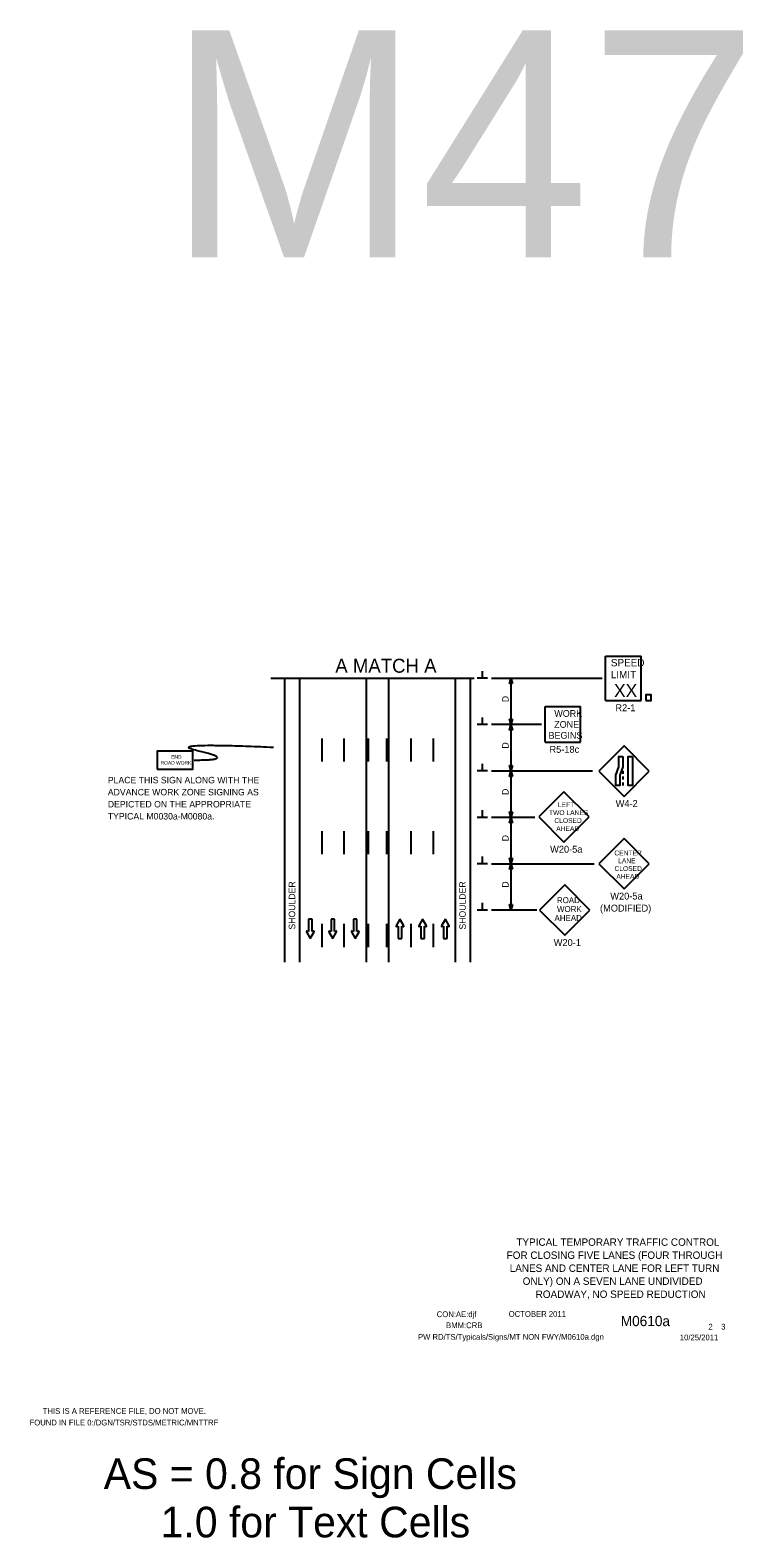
# Model space of a CAD drawing. Extents: x 16646 to 19498, y 2812 to 4437.
# Drawn here: x 17675 to 18443, y 2812 to 4437 of the extents above; entities that cross this region are included whole.
import ezdxf

# ---------------------------------------------------------------- set-up
doc = ezdxf.new("R2010")
doc.units = 0
for name, color, linetype in [('ALI_LEGAL_EX', 7, 'Continuous'), ('BORDER', 7, 'Continuous'), ('BORDER_SIGNAL_WO', 7, 'Continuous'), ('MT_SCRATCH_LEVEL_E', 7, 'Continuous'), ('PAVT_EDGE_EX', 7, 'Continuous'), ('SCRATCH_LEVEL_A', 7, 'Continuous'), ('TRAFFIC_SIGNS_PR', 7, 'Continuous'), ('TYPICAL_TEXT_DIMEN_PR', 7, 'Continuous')]:
    doc.layers.add(name, color=color, linetype=linetype)

msp = doc.modelspace()

# ---------------------------------------------------------------- linework, layer by layer
at = {"layer": 'ALI_LEGAL_EX'}
for points in [[(17989.2, 3673.8), (17989.2, 3648.8)], [(18013.2, 3673.8), (18013.2, 3648.8)], [(18039.2, 3673.8), (18039.2, 3648.8)], [(18059.2, 3673.8), (18059.2, 3648.8)], [(18085.2, 3673.8), (18085.2, 3648.8)], [(18109.2, 3673.8), (18109.2, 3648.8)], [(17989.2, 3573.8), (17989.2, 3548.8)], [(18013.2, 3573.8), (18013.2, 3548.8)], [(18039.2, 3573.8), (18039.2, 3548.8)], [(18059.2, 3573.8), (18059.2, 3548.8)], [(18085.2, 3573.8), (18085.2, 3548.8)], [(18109.2, 3573.8), (18109.2, 3548.8)], [(17989.2, 3473.8), (17989.2, 3448.8)], [(18013.2, 3473.8), (18013.2, 3448.8)], [(18039.2, 3473.8), (18039.2, 3448.8)], [(18059.2, 3473.8), (18059.2, 3448.8)], [(18085.2, 3473.8), (18085.2, 3448.8)], [(18109.2, 3473.8), (18109.2, 3448.8)]]:
    msp.add_lwpolyline(points, dxfattribs=at)
at = {"layer": 'MT_SCRATCH_LEVEL_E'}
for p, q in [((17972.7, 3465.1), (17976.8, 3457.9)), ((17972.7, 3465.1), (17976.8, 3457.9)), ((17974.9, 3465.5), (17973.1, 3465.8)), ((17974.9, 3465.5), (17973.1, 3465.8)), ((17978.7, 3478.8), (17974.9, 3478.8)), ((17974.9, 3478.8), (17974.9, 3465.5)), ((17978.7, 3478.8), (17974.9, 3478.8)), ((17974.9, 3478.8), (17974.9, 3465.5)), ((17976.8, 3457.9), (17980.9, 3465.1)), ((17976.8, 3457.9), (17980.9, 3465.1)), ((17978.7, 3465.5), (17978.7, 3478.8)), ((17978.7, 3465.5), (17978.7, 3478.8)), ((17980.4, 3465.8), (17978.7, 3465.5)), ((17980.4, 3465.8), (17978.7, 3465.5)), ((17996.9, 3465.1), (18001.1, 3457.9)), ((17996.9, 3465.1), (18001.1, 3457.9)), ((17999.2, 3465.5), (17997.4, 3465.8)), ((17999.2, 3465.5), (17997.4, 3465.8)), ((18002.9, 3478.8), (17999.2, 3478.8)), ((17999.2, 3478.8), (17999.2, 3465.5)), ((18002.9, 3478.8), (17999.2, 3478.8)), ((17999.2, 3478.8), (17999.2, 3465.5)), ((18001.1, 3457.9), (18005.2, 3465.1)), ((18001.1, 3457.9), (18005.2, 3465.1)), ((18002.9, 3465.5), (18002.9, 3478.8)), ((18002.9, 3465.5), (18002.9, 3478.8)), ((18004.7, 3465.8), (18002.9, 3465.5)), ((18004.7, 3465.8), (18002.9, 3465.5)), ((18021.2, 3465.1), (18025.3, 3457.9)), ((18021.2, 3465.1), (18025.3, 3457.9)), ((18023.4, 3465.5), (18021.6, 3465.8)), ((18023.4, 3465.5), (18021.6, 3465.8)), ((18027.2, 3478.8), (18023.4, 3478.8)), ((18023.4, 3478.8), (18023.4, 3465.5)), ((18027.2, 3478.8), (18023.4, 3478.8)), ((18023.4, 3478.8), (18023.4, 3465.5)), ((18025.3, 3457.9), (18029.4, 3465.1)), ((18025.3, 3457.9), (18029.4, 3465.1)), ((18027.2, 3465.5), (18027.2, 3478.8)), ((18027.2, 3465.5), (18027.2, 3478.8)), ((18028.9, 3465.8), (18027.2, 3465.5)), ((18028.9, 3465.8), (18027.2, 3465.5)), ((18073.5, 3478.8), (18069.4, 3471.5)), ((18073.5, 3478.8), (18069.4, 3471.5)), ((18069.9, 3470.8), (18071.6, 3471.1)), ((18069.9, 3470.8), (18071.6, 3471.1)), ((18071.6, 3471.1), (18071.6, 3457.9)), ((18071.6, 3471.1), (18071.6, 3457.9)), ((18077.6, 3471.5), (18073.5, 3478.8)), ((18077.6, 3471.5), (18073.5, 3478.8)), ((18075.4, 3457.9), (18075.4, 3471.1)), ((18075.4, 3471.1), (18077.2, 3470.8)), ((18075.4, 3457.9), (18075.4, 3471.1)), ((18075.4, 3471.1), (18077.2, 3470.8)), ((18098, 3478.8), (18093.9, 3471.5)), ((18098, 3478.8), (18093.9, 3471.5)), ((18094.4, 3470.8), (18096.1, 3471.1)), ((18094.4, 3470.8), (18096.1, 3471.1)), ((18096.1, 3471.1), (18096.1, 3457.9)), ((18096.1, 3471.1), (18096.1, 3457.9)), ((18102.1, 3471.5), (18098, 3478.8)), ((18102.1, 3471.5), (18098, 3478.8)), ((18099.9, 3457.9), (18099.9, 3471.1)), ((18099.9, 3471.1), (18101.6, 3470.8)), ((18099.9, 3457.9), (18099.9, 3471.1)), ((18099.9, 3471.1), (18101.6, 3470.8)), ((18122.5, 3478.8), (18118.4, 3471.5)), ((18122.5, 3478.8), (18118.4, 3471.5)), ((18118.8, 3470.8), (18120.6, 3471.1)), ((18118.8, 3470.8), (18120.6, 3471.1)), ((18120.6, 3471.1), (18120.6, 3457.9)), ((18120.6, 3471.1), (18120.6, 3457.9)), ((18126.6, 3471.5), (18122.5, 3478.8)), ((18126.6, 3471.5), (18122.5, 3478.8)), ((18124.4, 3457.9), (18124.4, 3471.1)), ((18124.4, 3471.1), (18126.1, 3470.8)), ((18124.4, 3457.9), (18124.4, 3471.1)), ((18124.4, 3471.1), (18126.1, 3470.8)), ((18071.6, 3457.9), (18075.4, 3457.9)), ((18071.6, 3457.9), (18075.4, 3457.9)), ((18096.1, 3457.9), (18099.9, 3457.9)), ((18096.1, 3457.9), (18099.9, 3457.9)), ((18120.6, 3457.9), (18124.4, 3457.9)), ((18120.6, 3457.9), (18124.4, 3457.9))]:
    msp.add_line(p, q, dxfattribs=at)
for centre, start, end in [((17973.1, 3465.4), 80.0362, 209.7731), ((17973.1, 3465.4), 80.0362, 209.7731), ((17980.5, 3465.4), 330.4248, 99.9638), ((17980.5, 3465.4), 330.4248, 99.9638), ((17997.3, 3465.4), 80.0362, 209.7731), ((17997.3, 3465.4), 80.0362, 209.7731), ((18004.8, 3465.4), 330.4248, 99.9638), ((18004.8, 3465.4), 330.4248, 99.9638), ((18021.6, 3465.4), 80.0362, 209.7731), ((18021.6, 3465.4), 80.0362, 209.7731), ((18029, 3465.4), 330.4248, 99.9638), ((18029, 3465.4), 330.4248, 99.9638), ((18069.8, 3471.3), 150.4248, 279.9638), ((18069.8, 3471.3), 150.4248, 279.9638), ((18077.2, 3471.3), 260.0362, 29.7731), ((18077.2, 3471.3), 260.0362, 29.7731), ((18094.3, 3471.3), 150.4248, 279.9638), ((18094.3, 3471.3), 150.4248, 279.9638), ((18101.7, 3471.3), 260.0362, 29.7731), ((18101.7, 3471.3), 260.0362, 29.7731), ((18118.8, 3471.3), 150.4248, 279.9638), ((18118.8, 3471.3), 150.4248, 279.9638), ((18126.2, 3471.3), 260.0362, 29.7731), ((18126.2, 3471.3), 260.0362, 29.7731)]:
    msp.add_arc(centre, 0.463, start, end, dxfattribs=at)
at = {"layer": 'PAVT_EDGE_EX'}
for p, q in [((17949.2, 3738.6), (17949.2, 3432.5)), ((17965.2, 3738.6), (17965.2, 3432.5)), ((18037.2, 3738.6), (18037.2, 3432.5)), ((18061.2, 3738.6), (18061.2, 3432.5)), ((18133.2, 3738.6), (18133.2, 3432.5)), ((18149.2, 3738.6), (18149.2, 3432.5))]:
    msp.add_line(p, q, dxfattribs=at)
at = {"layer": 'TRAFFIC_SIGNS_PR'}
for p, q in [((18295.3, 3762.6), (18333.7, 3762.6)), ((18295.3, 3714.6), (18295.3, 3762.6)), ((18333.7, 3714.6), (18333.7, 3762.6)), ((18230, 3669.6), (18230, 3708)), ((18230, 3708), (18268.4, 3708)), ((18268.4, 3669.6), (18268.4, 3708)), ((18295.3, 3714.6), (18333.7, 3714.6)), ((18230, 3669.6), (18268.4, 3669.6)), ((18315.3, 3665.6), (18288.1, 3638.4)), ((18342.4, 3638.4), (18315.3, 3665.6)), ((18288.1, 3638.4), (18315.3, 3611.2)), ((18314, 3638.9), (18314, 3635.7)), ((18314, 3632.5), (18314, 3629.3)), ((18314, 3626.1), (18314, 3622.9)), ((18315.3, 3611.2), (18342.4, 3638.4)), ((18250.4, 3616.3), (18223.2, 3589.1)), ((18277.5, 3589.1), (18250.4, 3616.3)), ((18223.2, 3589.1), (18250.4, 3562)), ((18250.4, 3562), (18277.5, 3589.1)), ((18315.3, 3565.8), (18288.1, 3538.6)), ((18342.4, 3538.6), (18315.3, 3565.8)), ((18288.1, 3538.6), (18315.3, 3511.5)), ((18315.3, 3511.5), (18342.4, 3538.6)), ((18251.3, 3515.8), (18224.1, 3488.6)), ((18278.4, 3488.6), (18251.3, 3515.8)), ((18224.1, 3488.6), (18251.3, 3461.4)), ((18251.3, 3461.4), (18278.4, 3488.6))]:
    msp.add_line(p, q, dxfattribs=at)
for points in [[(18338.7, 3714.6), (18344.3, 3714.6), (18344.3, 3720.7), (18338.7, 3720.7)], [(17811.8, 3640.7), (17850.2, 3640.7), (17850.2, 3659.9), (17811.8, 3659.9)], [(18314, 3654.1), (18314, 3643), (18310.7, 3634.1), (18310.7, 3622.9), (18306.2, 3622.9), (18306.2, 3634.1), (18309.5, 3643), (18309.5, 3654.1)], [(18324.2, 3654.1), (18324.2, 3622.9), (18319.7, 3622.9), (18319.7, 3654.1)]]:
    msp.add_lwpolyline(points, close=True, dxfattribs=at)
msp.add_open_spline([(17851.7, 3650.4), (17899, 3650.4), (17814, 3669.8), (17937, 3664.3)], degree=2, dxfattribs=at)
at = {"layer": 'TYPICAL_TEXT_DIMEN_PR'}
for p, q in [((18162.4, 3738.6), (18162.4, 3746.4)), ((17934.4, 3738.6), (18153.5, 3738.6)), ((18037.2, 3738.6), (18061.2, 3738.6)), ((18168, 3738.6), (18156.7, 3738.6)), ((18172.2, 3738.6), (18291.6, 3738.6)), ((18191.7, 3732.8), (18193.2, 3738.6)), ((18193.2, 3732.8), (18191.7, 3732.8)), ((18193.2, 3738.6), (18194.8, 3732.8)), ((18193.2, 3738.6), (18193.2, 3688.6)), ((18194.8, 3732.8), (18193.2, 3732.8)), ((18162.4, 3688.6), (18162.4, 3696.4)), ((18193.2, 3688.6), (18191.7, 3694.5)), ((18191.7, 3694.5), (18193.2, 3694.5)), ((18193.2, 3694.5), (18194.8, 3694.5)), ((18194.8, 3694.5), (18193.2, 3688.6)), ((18168, 3688.6), (18156.7, 3688.6)), ((18226.1, 3688.6), (18172.2, 3688.6)), ((18191.7, 3682.8), (18193.2, 3688.6)), ((18193.2, 3682.8), (18191.7, 3682.8)), ((18193.2, 3688.6), (18194.8, 3682.8)), ((18193.2, 3688.6), (18193.2, 3638.6)), ((18194.8, 3682.8), (18193.2, 3682.8)), ((18162.4, 3638.6), (18162.4, 3646.4)), ((18193.2, 3638.6), (18191.7, 3644.5)), ((18191.7, 3644.5), (18193.2, 3644.5)), ((18193.2, 3644.5), (18194.8, 3644.5)), ((18194.8, 3644.5), (18193.2, 3638.6)), ((18168, 3638.6), (18156.7, 3638.6)), ((18172.2, 3638.6), (18281.3, 3638.6)), ((18191.7, 3632.8), (18193.2, 3638.6)), ((18193.2, 3632.8), (18191.7, 3632.8)), ((18193.2, 3638.6), (18194.8, 3632.8)), ((18193.2, 3638.6), (18193.2, 3588.6)), ((18194.8, 3632.8), (18193.2, 3632.8)), ((18162.4, 3588.6), (18162.4, 3596.4)), ((18193.2, 3588.6), (18191.7, 3594.5)), ((18191.7, 3594.5), (18193.2, 3594.5)), ((18193.2, 3594.5), (18194.8, 3594.5)), ((18194.8, 3594.5), (18193.2, 3588.6)), ((18168, 3588.6), (18156.7, 3588.6)), ((18218.9, 3588.6), (18172.2, 3588.6)), ((18191.7, 3582.8), (18193.2, 3588.6)), ((18193.2, 3582.8), (18191.7, 3582.8)), ((18193.2, 3588.6), (18194.8, 3582.8)), ((18193.2, 3588.6), (18193.2, 3538.6)), ((18194.8, 3582.8), (18193.2, 3582.8)), ((18162.4, 3538.6), (18162.4, 3546.4)), ((18193.2, 3538.6), (18191.7, 3544.5)), ((18191.7, 3544.5), (18193.2, 3544.5)), ((18193.2, 3544.5), (18194.8, 3544.5)), ((18194.8, 3544.5), (18193.2, 3538.6)), ((18168, 3538.6), (18156.7, 3538.6)), ((18172.2, 3538.6), (18283.1, 3538.6)), ((18191.7, 3532.8), (18193.2, 3538.6)), ((18193.2, 3532.8), (18191.7, 3532.8)), ((18193.2, 3538.6), (18194.8, 3532.8)), ((18193.2, 3538.6), (18193.2, 3488.6)), ((18194.8, 3532.8), (18193.2, 3532.8)), ((18162.4, 3488.6), (18162.4, 3496.4)), ((18168, 3488.6), (18156.7, 3488.6)), ((18221.2, 3488.6), (18172.2, 3488.6)), ((18193.2, 3488.6), (18191.7, 3494.5)), ((18191.7, 3494.5), (18193.2, 3494.5)), ((18193.2, 3494.5), (18194.8, 3494.5)), ((18194.8, 3494.5), (18193.2, 3488.6))]:
    msp.add_line(p, q, dxfattribs=at)

# ---------------------------------------------------------------- texts
at = {"layer": 'BORDER'}
for s, p in [('TYPICAL TEMPORARY TRAFFIC CONTROL', (18199.1, 3126.6)), ('FOR CLOSING FIVE LANES (FOUR THROUGH', (18188.6, 3112.5)), ('LANES AND CENTER LANE FOR LEFT TURN', (18191.9, 3098.5)), ('ONLY) ON A SEVEN LANE UNDIVIDED', (18205.9, 3084.5)), ('ROADWAY, NO SPEED REDUCTION', (18219.9, 3070.4))]:
    msp.add_text(s, height=8.01, dxfattribs=at).set_placement(p)
at = {"layer": 'BORDER_SIGNAL_WO'}
for s, height, p in [('CON:AE:djf', 6.2, (18113.2, 3049.7)), ('BMM:CRB   ', 6.2, (18123.3, 3037.8)), ('    OCTOBER 2011    ', 6.2, (18181.6, 3050)), ('    M0610a   ', 11, (18295.3, 3040)), (' 2    3 ', 6.2, (18403.9, 3036.3)), ('PW RD/TS/Typicals/Signs/MT NON FWY/M0610a.dgn    ', 6.2, (18093, 3025.3)), ('10/25/2011    ', 6.2, (18375.4, 3024.7)), ('AS = 0.8 for Sign Cells', 33.03, (17754.1, 2864.4)), ('     1.0 for Text Cells', 33.03, (17754.1, 2812.2))]:
    msp.add_text(s, height=height, dxfattribs=at).set_placement(p)
at = {"layer": 'SCRATCH_LEVEL_A'}
for s, p in [('THIS IS A REFERENCE FILE, DO NOT MOVE.', (17688.3, 2945.4)), ('FOUND IN FILE 0:/DGN/TSR/STDS/METRIC/MNTTRF', (17674.1, 2932.9))]:
    msp.add_text(s, height=6.2, dxfattribs=at).set_placement(p)
at = {"layer": 'TRAFFIC_SIGNS_PR'}
for s, height, p in [('SPEED', 8, (18301, 3751.4)), ('LIMIT', 8, (18300.9, 3738.6)), ('XX', 14.03, (18304.4, 3718.3)), ('R2-1', 7.44, (18305.9, 3703.1)), ('WORK', 7.22, (18240, 3697)), ('ZONE', 7.22, (18239.9, 3685.2)), ('BEGINS', 7.22, (18233.8, 3673.4)), ('R5-18c', 7.44, (18234.8, 3658.2)), ('ROAD WORK', 3.83, (17815.4, 3645.5)), ('END', 3.83, (17826.8, 3651.9)), ('PLACE THIS SIGN ALONG WITH THE', 7, (17758.5, 3625.3)), ('ADVANCE WORK ZONE SIGNING AS', 7, (17758.5, 3612.3)), ('TYPICAL M0030a-M0080a.', 7, (17758.5, 3586.3)), ('DEPICTED ON THE APPROPRIATE', 7, (17758.5, 3599.3)), ('TWO LANES', 5.2, (18234.3, 3591.1)), ('LEFT', 5.2, (18243.9, 3599.7)), ('W4-2', 7.44, (18306.2, 3599.8)), ('CLOSED', 5.2, (18240.1, 3582.5)), ('AHEAD', 5.2, (18242.1, 3573.9)), ('W20-5a', 7.44, (18235.5, 3550.5)), ('CENTER', 5.2, (18304.8, 3547.6)), ('LANE', 5.2, (18308.9, 3539.2)), ('CLOSED', 5.2, (18304.9, 3530.8)), ('AHEAD', 5.2, (18306.9, 3522.4)), ('ROAD', 6.41, (18242.8, 3496.1)), ('W20-5a', 7.44, (18300.4, 3500)), ('AHEAD', 6.41, (18240.2, 3476.9)), ('WORK', 6.41, (18242.9, 3486.5)), ('(MODIFIED)', 7.44, (18289.3, 3487)), ('W20-1', 7.45, (18239.4, 3449.9))]:
    msp.add_text(s, height=height, dxfattribs=at).set_placement(p)
at = {"layer": 'TYPICAL_TEXT_DIMEN_PR'}
for s, height, p in [('M47', 245.04, (17822.4, 4192.4)), ('A MATCH A', 15, (18003.8, 3744.6))]:
    msp.add_text(s, height=height, dxfattribs=at).set_placement(p)
for s, p in [('D', (18190.7, 3712.8)), ('D', (18190.7, 3662.8)), ('D', (18190.7, 3612.8)), ('D', (18190.7, 3562.8)), ('SHOULDER', (17960.6, 3467.6)), ('SHOULDER', (18144.5, 3467.6)), ('D', (18190.7, 3512.8))]:
    msp.add_text(s, height=7, rotation=90, dxfattribs=at).set_placement(p)

doc.saveas('drawing.dxf')
